
// ===== library: MasterCopy "SIKO_AP20" =====

VAR_GLOBAL   // PLC tag table "SIKO_AP20"
   "Indicator1ControlWord" AT %QW2 : UInt;
   "Indicator1TargetValue" AT %QD4 : DInt;
   "Indicator1DisplayData" AT %QD8 : DInt;
   "Indicator1StatusWord" AT %IW2 : UInt;
   "Indicator1ActualValue" AT %ID4 : DInt;
   "Indicator1GenericMappingChannel" AT %ID8 : DInt;
   "Indicator1ErrorStatus" AT %IW12 : Int;
END_VAR

// ===== library: MasterCopy "SIKO_AP20_COM" =====

FUNCTION_BLOCK "SIKO_AP20_COM"   // FB403, SCL
TITLE = SIKO_AP20_COM
{ S7_Optimized_Access := 'TRUE' }
AUTHOR : SIKO_ch
FAMILY : EPN-Devices
NAME : 1.00
VERSION : 1.00
// Communication
   VAR_INPUT
      nTargetValue : DInt;
      nDisplayData : DInt;
      bc00 : Bool;
      bc01 : Bool;
      bc02 : Bool;
      bc03 : Bool;
      bc04 : Bool;
      bc05 : Bool;
      bc06 : Bool;
      bc07 : Bool;
      bc08 : Bool;
      bc09 : Bool;
      bc10 : Bool;
      bc11 : Bool;
      bc12 : Bool;
      bc13 : Bool;
      bc14 : Bool;
      bc15 : Bool;
      DC_nStatusWord : Word;
      varrStatusWord AT DC_nStatusWord : Array[0..15] of Bool;
      DC_nActualValue : DWord;
      DC_nGenMapCh : DWord;
      DC_nErrorStatus : Int;
   END_VAR
   VAR_OUTPUT
      nActualValue : DInt;
      bs00 : Bool;
      bs01 : Bool;
      bs02 : Bool;
      bs03 : Bool;
      bs04 : Bool;
      bs05 : Bool;
      bs06 : Bool;
      bs07 : Bool;
      bs08 : Bool;
      bs09 : Bool;
      bs10 : Bool;
      bs11 : Bool;
      bs12 : Bool;
      bs13 : Bool;
      bs14 : Bool;
      bs15 : Bool;
      nGenMapCh : DInt;
      nErrorStatus : Int;
      DC_nControlWord : Word;
      varrControlWord AT DC_nControlWord : Array[0..15] of Bool;
      DC_nTargetValue : DWord;
      DC_nDisplayData : DWord;
   END_VAR
BEGIN
   ////////////////////////////////////////////////////////////////////////////////////
   // Name: SIKO_AP20_COM
   ////////////////////////////////////////////////////////////////////////////////////
   // Version history
   ////////////////////////////////////////////////////////////////////////////////////
   // Date        | Vers. | created               | Author          | Remark
   // dd.mm.yyyy  |       | with                  |                 | 
   // ---------------------------------------------------------------------------------
   // 08.11.2018  | 0.01  | TIA V14 SP1 Upd5      | SIKO GmbH / ch  | alpha
   // 07.02.2019  | 0.02  | TIA V14 SP1 Upd5      | SIKO GmbH / ch  | alpha, Anpassungen an die Nomenklatur
   // 11.03.2019  | 1.00  | TIA V14 SP1 Upd5      | SIKO GmbH / ch  | first release
   ////////////////////////////////////////////////////////////////////////////////////

   // Actual Value
   #nActualValue := DWORD_TO_DINT(IN := #DC_nActualValue);

   // Generic Mapping Channel
   #nGenMapCh := DWORD_TO_DINT(IN := #DC_nGenMapCh);

   // Error Channel
   #nErrorStatus := #DC_nErrorStatus;

   // Status Word Bits
   #bs00 := #varrStatusWord[8];
   #bs01 := #varrStatusWord[9];
   #bs02 := #varrStatusWord[10];
   #bs03 := #varrStatusWord[11];
   #bs04 := #varrStatusWord[12];
   #bs05 := #varrStatusWord[13];
   #bs06 := #varrStatusWord[14];
   #bs07 := #varrStatusWord[15];
   #bs08 := #varrStatusWord[0];
   #bs09 := #varrStatusWord[1];
   #bs10 := #varrStatusWord[2];
   #bs11 := #varrStatusWord[3];
   #bs12 := #varrStatusWord[4];
   #bs13 := #varrStatusWord[5];
   #bs14 := #varrStatusWord[6];
   #bs15 := #varrStatusWord[7];

   // Target Value
   #DC_nTargetValue := DINT_TO_DWORD(IN := #nTargetValue);

   // Display Data
   #DC_nDisplayData := DINT_TO_DWORD(IN := #nDisplayData);

   // Control Word Bits 
   #varrControlWord[8] := #bc00;
   #varrControlWord[9] := #bc01;
   #varrControlWord[10] := #bc02;
   #varrControlWord[11] := #bc03;
   #varrControlWord[12] := #bc04;
   #varrControlWord[13] := #bc05;
   #varrControlWord[14] := #bc06;
   #varrControlWord[15] := #bc07;
   #varrControlWord[0] := #bc08;
   #varrControlWord[1] := #bc09;
   #varrControlWord[2] := #bc10;
   #varrControlWord[3] := #bc11;
   #varrControlWord[4] := #bc12;
   #varrControlWord[5] := #bc13;
   #varrControlWord[6] := #bc14;
   #varrControlWord[7] := #bc15;
END_FUNCTION_BLOCK

// ===== library: MasterCopy "SIKO_AP20_CSW_POS" =====

FUNCTION_BLOCK "SIKO_AP20_CSW_POS"   // FB404, SCL
TITLE = SIKO_AP20_CSW_POS
{ S7_Optimized_Access := 'TRUE' }
AUTHOR : SIKO_ch
FAMILY : EPN-Devices
NAME : 1.00
VERSION : 1.00
// Control-/Status word
   VAR_INPUT
      bc00_Cal : Bool;
      bc03_DisplayRange : Bool;
      bc05_ErrorAck : Bool;
      bc09_TargetValueActive : Bool;
      bc11_Led1Green : Bool;
      bc12_Led1Red : Bool;
      bc13_Led2Green : Bool;
      bc14_Led2Red : Bool;
      bc15_LedBlinking : Bool;
   END_VAR
   VAR_OUTPUT
      bs00_DirIndicationCW : Bool;
      bs01_DirIndicationCCW : Bool;
      bs02_CalExec : Bool;
      bs03_TarWinExtReached : Bool;
      bs05_TarWinReached : Bool;
      bs06_Deviation : Bool;
      bs07_GeneralError : Bool;
      bs09_IncMeasurement : Bool;
      bs10_TargetValueState : Bool;
      bs11_BatteryState : Bool;
      bs12_SensorError : Bool;
      bs13_KeyConfiguration : Bool;
      bs14_KeyCalibration : Bool;
      bs15_KeyIncremental : Bool;
   END_VAR
   VAR_IN_OUT
      DC_Com : "SIKO_AP20_COM";
   END_VAR
BEGIN
   ////////////////////////////////////////////////////////////////////////////////////
   // Name: SIKO_AP20_CSW_POS
   ////////////////////////////////////////////////////////////////////////////////////
   // Version history
   ////////////////////////////////////////////////////////////////////////////////////
   // Date        | Vers. | created               | Author          | Remark
   // dd.mm.yyyy  |       | with                  |                 | 
   // ---------------------------------------------------------------------------------
   // 08.11.2018  | 0.01  | TIA V14 SP1 Upd5      | SIKO GmbH / ch  | alpha
   // 07.02.2019  | 0.02  | TIA V14 SP1 Upd5      | SIKO GmbH / ch  | alpha, Anpassungen an die Nomenklatur
   // 11.03.2019  | 1.00  | TIA V14 SP1 Upd5      | SIKO GmbH / ch  | first release
   ////////////////////////////////////////////////////////////////////////////////////

   ////////////////////////////////////////////////////////////////////////////////////
   // status word
   //
   #bs00_DirIndicationCW := #DC_Com.bs00;
   #bs01_DirIndicationCCW := #DC_Com.bs01;
   #bs02_CalExec := #DC_Com.bs02;
   #bs03_TarWinExtReached := #DC_Com.bs03;
   // bs04: Reserved
   #bs05_TarWinReached := #DC_Com.bs05;
   #bs06_Deviation := #DC_Com.bs06;
   #bs07_GeneralError := #DC_Com.bs07;
   // bs08: Reserved
   #bs09_IncMeasurement := #DC_Com.bs09;
   #bs10_TargetValueState := #DC_Com.bs10;
   #bs11_BatteryState := #DC_Com.bs11;
   #bs12_SensorError := #DC_Com.bs12;
   #bs13_KeyConfiguration := #DC_Com.bs13;
   #bs14_KeyCalibration := #DC_Com.bs14;
   #bs15_KeyIncremental := #DC_Com.bs15;

   ///////////////////////////////////////////////////////////////////////////////////////////////
   // control word
   //
   #DC_Com.bc00 := #bc00_Cal;
   #DC_Com.bc01 := 0; // Reserved, ever 0
   #DC_Com.bc02 := 0; // Reserved, ever 0
   #DC_Com.bc03 := #bc03_DisplayRange;
   #DC_Com.bc04 := 0; // Reserved, ever 0
   #DC_Com.bc05 := #bc05_ErrorAck;
   #DC_Com.bc06 := 0; // Reserved, ever 0
   #DC_Com.bc07 := 0; // Reserved, ever 0
   #DC_Com.bc08 := 0; // Reserved, ever 0
   #DC_Com.bc09 := #bc09_TargetValueActive;
   #DC_Com.bc10 := 0; // Reserved, ever 0
   #DC_Com.bc11 := #bc11_Led1Green;
   #DC_Com.bc12 := #bc12_Led1Red;
   #DC_Com.bc13 := #bc13_Led2Green;
   #DC_Com.bc14 := #bc14_Led2Red;
   #DC_Com.bc15 := #bc15_LedBlinking;
END_FUNCTION_BLOCK

// ===== library: MasterCopy "SIKO_AP20_CSW_TXT" =====

FUNCTION_BLOCK "SIKO_AP20_CSW_TXT"   // FB405, SCL
TITLE = SIKO_AP20_CSW_TXT
{ S7_Optimized_Access := 'TRUE' }
AUTHOR : SIKO_ch
FAMILY : EPN-Devices
NAME : 1.00
VERSION : 1.00
// Control-/Status word
   VAR_INPUT
      bc02_DisplayDataActive : Bool;
      bc03_DisplayRange : Bool;
      bc05_ErrorAck : Bool;
      bc06_TargetValueAckMode : Bool;
      bc07_TargetValueTypeSelect : Bool;
      bc08_DisplayDataTypeSelect : Bool;
      bc09_TargetValueActive : Bool;
      bc10_DisplayDataAckMode : Bool;
      bc11_Led1Green : Bool;
      bc12_Led1Red : Bool;
      bc13_Led2Green : Bool;
      bc14_Led2Red : Bool;
      bc15_LedBlinking : Bool;
   END_VAR
   VAR_OUTPUT
      bs02_DisplayDataState : Bool;
      bs03_TargetValueAck : Bool;
      bs05_DisplayDataAck : Bool;
      bs07_GeneralError : Bool;
      bs08_DisplayDataType : Bool;
      bs09_TargetValueType : Bool;
      bs10_TargetValueState : Bool;
      bs11_BatteryState : Bool;
      bs12_SensorError : Bool;
      bs13_KeyConfiguration : Bool;
      bs14_KeyCalibration : Bool;
      bs15_KeyIncremental : Bool;
   END_VAR
   VAR_IN_OUT
      DC_Com : "SIKO_AP20_COM";
   END_VAR
BEGIN
   ////////////////////////////////////////////////////////////////////////////////////
   // Name: SIKO_AP20_CSW_TXT
   ////////////////////////////////////////////////////////////////////////////////////
   // Version history
   ////////////////////////////////////////////////////////////////////////////////////
   // Date        | Vers. | created               | Author          | Remark
   // dd.mm.yyyy  |       | with                  |                 | 
   // ---------------------------------------------------------------------------------
   // 08.11.2018  | 0.01  | TIA V14 SP1 Upd5      | SIKO GmbH / ch  | alpha
   // 07.02.2019  | 0.02  | TIA V14 SP1 Upd5      | SIKO GmbH / ch  | alpha, Anpassungen an die Nomenklatur
   // 11.03.2019  | 1.00  | TIA V14 SP1 Upd5      | SIKO GmbH / ch  | first release
   ////////////////////////////////////////////////////////////////////////////////////

   ////////////////////////////////////////////////////////////////////////////////////
   // status word
   //
   // bs00: Reserved
   // bs01: Reserved
   #bs02_DisplayDataState := #DC_Com.bs02;
   #bs03_TargetValueAck := #DC_Com.bs03;
   // bs04: Reserved
   #bs05_DisplayDataAck := #DC_Com.bs05;
   // bs06: Reserved
   #bs07_GeneralError := #DC_Com.bs07;
   #bs08_DisplayDataType := #DC_Com.bs08;
   #bs09_TargetValueType := #DC_Com.bs09;
   #bs10_TargetValueState := #DC_Com.bs10;
   #bs11_BatteryState := #DC_Com.bs11;
   #bs12_SensorError := #DC_Com.bs12;
   #bs13_KeyConfiguration := #DC_Com.bs13;
   #bs14_KeyCalibration := #DC_Com.bs14;
   #bs15_KeyIncremental := #DC_Com.bs15;

   ////////////////////////////////////////////////////////////////////////////////////
   // control word
   //
   #DC_Com.bc00 := 0; // Reserved, ever 0
   #DC_Com.bc01 := 0; // Reserved, ever 0
   #DC_Com.bc02 := #bc02_DisplayDataActive;
   #DC_Com.bc03 := #bc03_DisplayRange;
   #DC_Com.bc04 := 0; // Reserved, ever 0
   #DC_Com.bc05 := #bc05_ErrorAck;
   #DC_Com.bc06 := #bc06_TargetValueAckMode;
   #DC_Com.bc07 := #bc07_TargetValueTypeSelect;
   #DC_Com.bc08 := #bc08_DisplayDataTypeSelect;
   #DC_Com.bc09 := #bc09_TargetValueActive;
   #DC_Com.bc10 := #bc10_DisplayDataAckMode;
   #DC_Com.bc11 := #bc11_Led1Green;
   #DC_Com.bc12 := #bc12_Led1Red;
   #DC_Com.bc13 := #bc13_Led2Green;
   #DC_Com.bc14 := #bc14_Led2Red;
   #DC_Com.bc15 := #bc15_LedBlinking;
END_FUNCTION_BLOCK

// ===== library: MasterCopy "SIKO_AP20_PRM" =====

FUNCTION_BLOCK "SIKO_AP20_PRM"   // FB406, SCL
TITLE = SIKO_AP20_PRM
{ S7_Optimized_Access := 'TRUE' }
AUTHOR : SIKO_ch
FAMILY : EPN-Devices
NAME : 1.01
VERSION : 1.01
// Parameter access
   VAR_INPUT
      DC_nHwId : Hw_Io;
      nIndex : DInt;
      bcReadWrite : Bool;
      nWriteValue : DInt;
      bcExecute : Bool;
   END_VAR
   VAR_OUTPUT
      bsBusy : Bool;
      bsError : Bool;
      bsDone : Bool;
      nStatus : DWord;
      nReceiveValue : DInt;
   END_VAR
   VAR
      DC_DataBuffer : DWord;
      varrDataBuffer AT DC_DataBuffer : Array[0..3] of Byte;
      vbOsfReadBusy : Bool;
      vbMemReadBusy : Bool;
      vbOsfWriteBusy : Bool;
      vbMemWriteBusy : Bool;
      vbOsrExecute : Bool;
      vbMemExecute : Bool;
      fbRDREC1 : RDREC;
      vbReadValid : Bool;
      vbReadBusy : Bool;
      vbReadError : Bool;
      vnReadStatus : DWord;
      vnReadIndex : DInt;
      vbReadEnable : Bool;
      vnReadLength : UInt;
      vnReadState : UInt;
      fbWRREC_1 : WRREC;
      vbWriteDone : Bool;
      vbWriteBusy : Bool;
      vbWriteError : Bool;
      vnWriteStatus : DWord;
      vnWriteIndex : DInt;
      vbWriteEnable : Bool;
      vnWriteLength : UInt;
      vnWriteState : UInt;
      vbWriteCommand : Bool;
      vnDataLength : UInt;
   END_VAR
BEGIN
   ////////////////////////////////////////////////////////////////////////////////////
   // Name: SIKO_AP20_PRM
   ////////////////////////////////////////////////////////////////////////////////////
   // Version history
   ////////////////////////////////////////////////////////////////////////////////////
   // Date        | Vers. | created               | Author          | Remark
   // dd.mm.yyyy  |       | with                  |                 | 
   // ---------------------------------------------------------------------------------
   // 11.03.2019  | 1.00  | TIA V14 SP1 Upd5      | SIKO GmbH / ch  | first release
   // 21.05.2019  | 1.01  | TIA V14 SP1 Upd5      | SIKO GmbH / ch  | bugfix data type handling

   ////////////////////////////////////////////////////////////////////////////////////
   // Init
   IF (#nIndex = 0) AND NOT #bcExecute THEN
       #bsDone := 0;
       #bsBusy := 0;
       #bsError := 0;
       #nStatus := 0;
       #vbOsrExecute := 0;
       #vbMemExecute := 0;
       #vbWriteCommand := 0;
       #nReceiveValue := 0;
       #DC_DataBuffer := 0;
   END_IF;

   ///////////////////////////////////////////////////////////////////////////////////////////////
   // new command on rising edge
   //
   IF #vbOsrExecute THEN
       #bsDone := 0;
       #bsBusy := 1;
       #bsError := 0;
       #nStatus := 0;

       IF (#bcReadWrite) THEN
           // write command
           #vbWriteCommand := 1;
       ELSE
           // read command
           #vbWriteCommand := 0;
       END_IF;

       //always start with read request
       #vnReadState := 1;
   END_IF;

   CASE #vnReadState OF
       1: // Start RDREC
           #vnReadIndex := #nIndex;
           #vbReadEnable := TRUE;
           // clear input buffer
           #DC_DataBuffer := 0;
           #nReceiveValue := 0;
           #vnReadState := 2;
       2: // Check for errors, copy output
           IF NOT #vbReadBusy THEN
               #vbReadEnable := FALSE;
               #vnReadState := 0;
               IF #vbReadError THEN
                   #bsBusy := FALSE;
                   #bsError := TRUE;
                   #bsDone := FALSE;
                   #nStatus := #vnReadStatus;
               ELSIF #vbReadValid THEN
                   (* Data Valid *)
                   #nStatus := #vnReadStatus;
                   #vnDataLength := #vnReadLength;

                   IF (#vbWriteCommand) THEN
                       #vnWriteState := 1;
                   ELSE
                       // ab V1.01 Korrekte Verarbeitung der Datentypen
                       IF (#vnReadLength = 1) THEN
                           #nReceiveValue := BYTE_TO_DINT(SHR(IN := #DC_DataBuffer, N := 24));
                       ELSIF (#vnReadLength = 2) THEN
                           (* Integer16 representation of Index 8 and 45 *)
                           IF (#nIndex = 8) OR (#nIndex = 45) THEN
                               #nReceiveValue := INT_TO_DINT(SHR(IN := #DC_DataBuffer, N := 16));
                           ELSE
                               #nReceiveValue := UINT_TO_DINT(SHR(IN := #DC_DataBuffer, N := 16));
                           END_IF;
                       ELSE
                           #nReceiveValue := DWORD_TO_DINT(#DC_DataBuffer);
                       END_IF;
                       // set status bits
                       #bsDone := TRUE;
                       #bsBusy := FALSE;
                       #bsError := FALSE;
                       #nStatus := 0;
                   END_IF;
               END_IF;
           END_IF;
   END_CASE;

   // Handle Parameter Write Command
   CASE #vnWriteState OF
       1: // Start WRREC
           #vnWriteIndex := #nIndex;
           #vnWriteLength := #vnDataLength;
           #vbWriteEnable := TRUE;
           // ab V1.01 Korrekte Verarbeitung der Datentypen
           IF (#vnWriteLength = 1) THEN
               #DC_DataBuffer := SHL(IN := DINT_TO_DWORD(#nWriteValue), N := 24);
           ELSIF (#vnWriteLength = 2) THEN
               #DC_DataBuffer := SHL(IN := DINT_TO_DWORD(#nWriteValue), N := 16);
           ELSIF (#vnWriteLength = 4) THEN
               #DC_DataBuffer := DINT_TO_DWORD(#nWriteValue);
           END_IF;
           #vnWriteState := 2;
       2: // Check for errors, copy output
           IF NOT #vbWriteBusy THEN
               #vnWriteState := 0;
               #vbWriteEnable := FALSE;
               IF #vbWriteError THEN
                   #bsBusy := FALSE;
                   #bsError := TRUE;
                   #bsDone := FALSE;
                   #nStatus := #vnWriteStatus;
               ELSIF #vbWriteDone THEN
                   (* Transfer successful *)
                   #nReceiveValue := #nWriteValue;
                   #bsBusy := FALSE;
                   #bsError := FALSE;
                   #bsDone := TRUE;
                   #nStatus := #vnWriteStatus;
               END_IF;
           END_IF;
   END_CASE;

   // Read Record
   #fbRDREC1(ID := #DC_nHwId,
             INDEX := #vnReadIndex,
             MLEN := 4,
             REQ := #vbReadEnable,
             RECORD := #varrDataBuffer,
             VALID => #vbReadValid,
             BUSY => #vbReadBusy,
             ERROR => #vbReadError,
             STATUS => #vnReadStatus,
             LEN => #vnReadLength);

   // Write Record
   #fbWRREC_1(ID := #DC_nHwId,
              INDEX := #vnWriteIndex,
              LEN := #vnWriteLength,
              REQ := #vbWriteEnable,
              RECORD := #varrDataBuffer,
              BUSY => #vbWriteBusy,
              ERROR => #vbWriteError,
              DONE => #vbWriteDone,
              STATUS => #vnWriteStatus);

   // vbReadBusy: falling edge
   #vbOsfReadBusy := NOT #vbReadBusy AND #vbMemReadBusy;
   #vbMemReadBusy := #vbReadBusy;

   // #vbWriteBusy: falling edge 
   #vbOsfWriteBusy := NOT #vbWriteBusy AND #vbMemWriteBusy;
   #vbMemWriteBusy := #vbWriteBusy;

   // bcExecute: rising edge
   #vbOsrExecute := #bcExecute AND NOT #vbMemExecute;
   #vbMemExecute := #bcExecute;
END_FUNCTION_BLOCK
